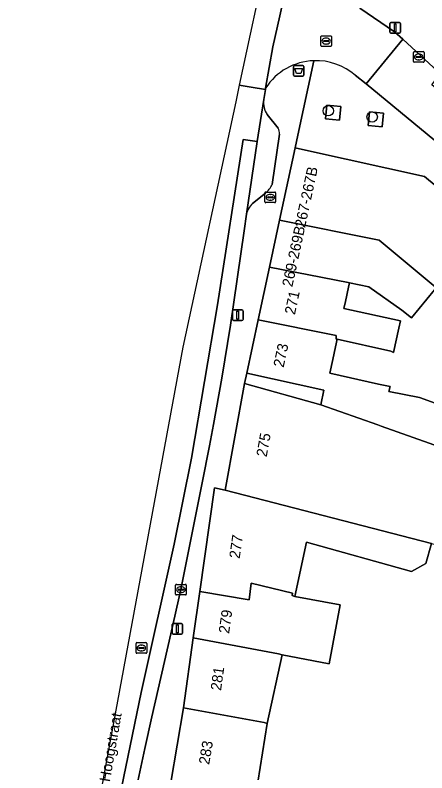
# Model space of a CAD drawing. Extents: x 160157 to 160921, y 381516 to 382045.
# Drawn here: x 160276.1 to 160314.8, y 381893.9 to 381965.1 of the extents above; entities that cross this region are included whole.
import ezdxf

# ---------------------------------------------------------------- set-up
doc = ezdxf.new("R2010")
doc.units = 0
for name, color, linetype in [('IMGEO_Afvalbak', 7, 'Continuous'), ('IMGEO_Boom', 7, 'Continuous'), ('IMGEO_Erf', 7, 'Continuous'), ('IMGEO_Kolk', 7, 'Continuous'), ('IMGEO_Lichtmast', 7, 'Continuous'), ('IMGEO_Openbare_ruimte_label', 7, 'Continuous'), ('IMGEO_Pand', 7, 'Continuous'), ('IMGEO_Pand_nummerreeks', 7, 'Continuous'), ('IMGEO_Parkeervlak_open', 7, 'Continuous'), ('IMGEO_Rijbaan_lokaal_gesloten', 7, 'Continuous'), ('IMGEO_Rijbaan_lokaal_open', 7, 'Continuous'), ('IMGEO_Rioolput', 7, 'Continuous'), ('IMGEO_Verkeerseiland_groen', 7, 'Continuous'), ('IMGEO_Voetpad_open', 7, 'Continuous')]:
    doc.layers.add(name, color=color, linetype=linetype)

msp = doc.modelspace()

# ---------------------------------------------------------------- linework, layer by layer
at = {"layer": 'IMGEO_Afvalbak'}
for p, q in [((160302.243, 381959.444), (160302.243, 381960.244)), ((160302.243, 381960.244), (160302.243, 381959.444)), ((160302.343, 381960.344), (160303.133, 381960.344)), ((160303.133, 381960.344), (160302.343, 381960.344)), ((160303.233, 381960.244), (160303.233, 381959.444)), ((160303.233, 381959.444), (160303.233, 381960.244)), ((160303.133, 381959.344), (160302.343, 381959.344)), ((160302.343, 381959.344), (160303.133, 381959.344))]:
    msp.add_line(p, q, dxfattribs=at)
msp.add_lwpolyline([(160302.386, 381960.058), (160303.09, 381960.058), (160302.941, 381959.588), (160302.535, 381959.588), (160302.386, 381960.058)], dxfattribs=at)
for centre, start, end in [((160302.343, 381960.244), 90, 180), ((160302.343, 381960.244), 90, 180), ((160303.133, 381960.244), 0, 90), ((160303.133, 381960.244), 360, 90), ((160302.343, 381959.444), 180, 270), ((160302.343, 381959.444), 180, 270), ((160303.133, 381959.444), 270, 0), ((160303.133, 381959.444), 270, 0)]:
    msp.add_arc(centre, 0.1, start, end, dxfattribs=at)
at = {"layer": 'IMGEO_Boom'}
for centre in [(160305.523, 381956.101), (160309.643, 381955.512)]:
    msp.add_circle(centre, 0.489, dxfattribs=at)
at = {"layer": 'IMGEO_Erf'}
for points in [[(160315.504, 381939.276), (160313.335, 381936.645), (160312.439, 381937.379), (160309.331, 381939.549), (160307.525, 381939.949), (160307.431, 381939.523), (160307.137, 381938.195), (160306.991, 381937.531), (160312.301, 381936.356), (160312.154, 381935.692), (160311.645, 381933.391), (160311.405, 381933.518), (160306.362, 381934.633), (160306.209, 381933.943), (160306.074, 381933.334), (160305.939, 381932.725), (160305.656, 381931.448), (160310.237, 381930.434), (160311.319, 381930.195), (160311.218, 381929.737), (160314.104, 381929.169), (160323.234, 381925.853)], [(160315.222, 381915.474), (160314.69, 381913.569), (160313.339, 381912.824), (160303.485, 381915.581), (160302.383, 381910.492), (160306.634, 381909.694), (160305.597, 381904.174), (160301.195, 381905.001), (160299.796, 381898.547), (160298.67, 381891.657)]]:
    msp.add_lwpolyline(points, dxfattribs=at)
msp.add_lwpolyline([(160297.869, 381931.467), (160297.644, 381930.479), (160304.815, 381928.497), (160305.117, 381929.863)], close=True, dxfattribs=at)
at = {"layer": 'IMGEO_Kolk'}
for p, q in [((160313.521, 381960.724), (160313.521, 381961.576)), ((160313.596, 381961.65), (160314.448, 381961.65)), ((160314.009, 381961.43), (160314.034, 381961.43)), ((160314.522, 381961.576), (160314.522, 381960.724)), ((160314.448, 381960.65), (160313.596, 381960.65)), ((160313.78, 381961.144), (160313.78, 381961.156)), ((160314.218, 381961.107), (160313.82, 381961.107)), ((160313.823, 381961.193), (160314.221, 381961.193)), ((160314.032, 381960.87), (160314.007, 381960.87)), ((160314.264, 381961.156), (160314.264, 381961.144)), ((160299.647, 381948.466), (160300.499, 381948.466)), ((160299.572, 381947.54), (160299.572, 381948.392)), ((160299.831, 381947.96), (160299.831, 381947.972)), ((160300.269, 381947.923), (160299.871, 381947.923)), ((160299.874, 381948.009), (160300.272, 381948.009)), ((160300.06, 381948.246), (160300.085, 381948.246)), ((160300.315, 381947.972), (160300.315, 381947.96)), ((160300.573, 381948.392), (160300.573, 381947.54)), ((160300.499, 381947.466), (160299.647, 381947.466)), ((160300.083, 381947.686), (160300.058, 381947.686)), ((160291.178, 381910.7), (160291.178, 381911.552)), ((160291.253, 381911.626), (160292.105, 381911.626)), ((160292.179, 381911.552), (160292.179, 381910.7)), ((160291.437, 381911.12), (160291.437, 381911.132)), ((160291.875, 381911.083), (160291.477, 381911.083)), ((160291.48, 381911.169), (160291.878, 381911.169)), ((160291.689, 381910.846), (160291.664, 381910.846)), ((160291.666, 381911.406), (160291.691, 381911.406)), ((160291.921, 381911.132), (160291.921, 381911.12)), ((160292.105, 381910.626), (160291.253, 381910.626))]:
    msp.add_line(p, q, dxfattribs=at)
for points in [[(160313.521, 381960.724), (160313.521, 381961.576)], [(160313.596, 381961.65), (160314.448, 381961.65)], [(160314.522, 381961.576), (160314.522, 381960.724)], [(160314.448, 381960.65), (160313.596, 381960.65)], [(160299.647, 381948.466), (160300.499, 381948.466)], [(160299.572, 381947.54), (160299.572, 381948.392)], [(160300.573, 381948.392), (160300.573, 381947.54)], [(160300.499, 381947.466), (160299.647, 381947.466)], [(160291.178, 381910.7), (160291.178, 381911.552)], [(160291.253, 381911.626), (160292.105, 381911.626)], [(160292.179, 381911.552), (160292.179, 381910.7)], [(160292.105, 381910.626), (160291.253, 381910.626)]]:
    msp.add_lwpolyline(points, dxfattribs=at)
for centre, radius, start, end in [((160313.598, 381961.574), 0.0765, 91.55205, 178.44795), ((160313.598, 381961.574), 0.0765, 91.55205, 178.44795), ((160314.446, 381961.574), 0.0765, 1.55205, 88.44795), ((160314.446, 381961.574), 0.0765, 1.55205, 88.44795), ((160313.598, 381960.726), 0.0765, 181.55205, 268.44795), ((160313.598, 381960.726), 0.0765, 181.55205, 268.44795), ((160313.82, 381961.153), 0.0403, 85.87752, 175.75265), ((160313.817, 381961.143), 0.0366, 178.93798, 274.71019), ((160314.221, 381961.15), 0.043, 264.86636, 352.45326), ((160314.225, 381961.155), 0.0386, 1.73085, 96.63898), ((160314.446, 381960.726), 0.0765, 271.55205, 358.44795), ((160314.446, 381960.726), 0.0765, 271.55205, 358.44795), ((160299.649, 381948.39), 0.0765, 91.55205, 178.44795), ((160299.649, 381948.39), 0.0765, 91.55205, 178.44795), ((160300.497, 381948.39), 0.0765, 1.55205, 88.44795), ((160300.497, 381948.39), 0.0765, 1.55205, 88.44795), ((160299.871, 381947.969), 0.0403, 85.87752, 175.75265), ((160299.868, 381947.959), 0.0366, 178.93798, 274.71019), ((160300.272, 381947.966), 0.043, 264.86636, 352.45326), ((160300.276, 381947.971), 0.0386, 1.73085, 96.63898), ((160299.649, 381947.542), 0.0765, 181.55205, 268.44795), ((160299.649, 381947.542), 0.0765, 181.55205, 268.44795), ((160300.497, 381947.542), 0.0765, 271.55205, 358.44795), ((160300.497, 381947.542), 0.0765, 271.55205, 358.44795), ((160291.255, 381911.55), 0.0765, 91.55205, 178.44795), ((160291.255, 381911.55), 0.0765, 91.55205, 178.44795), ((160292.103, 381911.55), 0.0765, 1.55205, 88.44795), ((160292.103, 381911.55), 0.0765, 1.55205, 88.44795), ((160291.477, 381911.129), 0.0403, 85.87752, 175.75265), ((160291.474, 381911.119), 0.0366, 178.93798, 274.71019), ((160291.878, 381911.126), 0.043, 264.86636, 352.45326), ((160291.882, 381911.131), 0.0386, 1.73085, 96.63898), ((160291.255, 381910.702), 0.0765, 181.55205, 268.44795), ((160291.255, 381910.702), 0.0765, 181.55205, 268.44795), ((160292.103, 381910.702), 0.0765, 271.55205, 358.44795), ((160292.103, 381910.702), 0.0765, 271.55205, 358.44795)]:
    msp.add_arc(centre, radius, start, end, dxfattribs=at)
for centre, major_axis, ratio, start_param, end_param in [((160314.008, 381961.15), (-0.387, 0.002), 0.722429, 4.712389, 7.853982), ((160314.033, 381961.15), (-0.39, 0.002), 0.717154, 1.570796, 4.712389), ((160300.059, 381947.966), (-0.387, 0.002), 0.722429, 4.712389, 7.853982), ((160300.084, 381947.966), (-0.39, 0.002), 0.717154, 1.570796, 4.712389), ((160291.665, 381911.126), (-0.387, 0.002), 0.722429, 4.712389, 7.853982), ((160291.69, 381911.126), (-0.39, 0.002), 0.717154, 1.570796, 4.712389)]:
    msp.add_ellipse(centre, major_axis=major_axis, ratio=ratio, start_param=start_param, end_param=end_param, dxfattribs=at)
at = {"layer": 'IMGEO_Lichtmast'}
for p, q in [((160311.309, 381963.491), (160311.309, 381964.291)), ((160311.309, 381964.291), (160311.309, 381963.491)), ((160311.409, 381964.391), (160312.199, 381964.391)), ((160312.199, 381964.391), (160311.409, 381964.391)), ((160312.299, 381964.291), (160312.299, 381963.491)), ((160312.299, 381963.491), (160312.299, 381964.291)), ((160312.199, 381963.391), (160311.409, 381963.391)), ((160311.409, 381963.391), (160312.199, 381963.391)), ((160296.526, 381936.491), (160296.526, 381937.291)), ((160296.526, 381937.291), (160296.526, 381936.491)), ((160296.626, 381937.391), (160297.416, 381937.391)), ((160297.416, 381937.391), (160296.626, 381937.391)), ((160297.516, 381937.291), (160297.516, 381936.491)), ((160297.516, 381936.491), (160297.516, 381937.291)), ((160297.416, 381936.391), (160296.626, 381936.391)), ((160296.626, 381936.391), (160297.416, 381936.391)), ((160290.95, 381907.951), (160291.74, 381907.951)), ((160291.74, 381907.951), (160290.95, 381907.951)), ((160290.85, 381907.051), (160290.85, 381907.851)), ((160290.85, 381907.851), (160290.85, 381907.051)), ((160291.84, 381907.851), (160291.84, 381907.051)), ((160291.84, 381907.051), (160291.84, 381907.851)), ((160291.74, 381906.951), (160290.95, 381906.951)), ((160290.95, 381906.951), (160291.74, 381906.951))]:
    msp.add_line(p, q, dxfattribs=at)
for points in [[(160311.729, 381964.266), (160311.879, 381964.266), (160311.879, 381963.516), (160311.729, 381963.516), (160311.729, 381964.266)], [(160296.946, 381937.266), (160297.096, 381937.266), (160297.096, 381936.516), (160296.946, 381936.516), (160296.946, 381937.266)], [(160291.27, 381907.826), (160291.42, 381907.826), (160291.42, 381907.076), (160291.27, 381907.076), (160291.27, 381907.826)]]:
    msp.add_lwpolyline(points, dxfattribs=at)
for centre, start, end in [((160311.409, 381964.291), 90, 180), ((160311.409, 381964.291), 90, 180), ((160312.199, 381964.291), 0, 90), ((160312.199, 381964.291), 360, 90), ((160311.409, 381963.491), 180, 270), ((160311.409, 381963.491), 180, 270), ((160312.199, 381963.491), 270, 0), ((160312.199, 381963.491), 270, 0), ((160296.626, 381937.291), 90, 180), ((160296.626, 381937.291), 90, 180), ((160297.416, 381937.291), 0, 90), ((160297.416, 381937.291), 360, 90), ((160296.626, 381936.491), 180, 270), ((160296.626, 381936.491), 180, 270), ((160297.416, 381936.491), 270, 0), ((160297.416, 381936.491), 270, 0), ((160290.95, 381907.851), 90, 180), ((160290.95, 381907.851), 90, 180), ((160291.74, 381907.851), 0, 90), ((160291.74, 381907.851), 360, 90), ((160290.95, 381907.051), 180, 270), ((160290.95, 381907.051), 180, 270), ((160291.74, 381907.051), 270, 0), ((160291.74, 381907.051), 270, 0)]:
    msp.add_arc(centre, 0.1, start, end, dxfattribs=at)
at = {"layer": 'IMGEO_Pand'}
for points in [[(160314.547, 381949.911), (160303.648, 381952.346), (160302.402, 381952.62), (160300.943, 381945.827), (160310.305, 381943.95), (160315.932, 381939.263), (160317.394, 381941.086), (160320.396, 381944.729), (160320.573, 381944.944)], [(160310.305, 381943.95), (160300.943, 381945.827), (160299.997, 381941.422), (160307.388, 381939.979), (160307.525, 381939.949), (160309.331, 381939.549), (160312.439, 381937.379), (160313.335, 381936.645), (160315.504, 381939.276), (160315.768, 381939.058), (160315.932, 381939.263)], [(160307.431, 381939.523), (160307.525, 381939.949), (160307.388, 381939.979), (160299.997, 381941.422), (160298.94, 381936.479), (160306.273, 381935.002), (160306.247, 381934.658), (160306.362, 381934.633), (160311.405, 381933.518), (160311.645, 381933.391), (160312.154, 381935.692), (160312.301, 381936.356), (160306.991, 381937.531), (160307.137, 381938.195)], [(160306.362, 381934.633), (160306.247, 381934.658), (160306.273, 381935.002), (160298.94, 381936.479), (160297.869, 381931.467), (160305.117, 381929.863), (160304.815, 381928.497), (160310.186, 381926.596), (160310.498, 381926.485), (160320.481, 381922.951), (160321.987, 381922.418), (160323.234, 381925.853), (160314.104, 381929.169), (160311.218, 381929.737), (160311.319, 381930.195), (160310.237, 381930.434), (160305.656, 381931.448), (160305.939, 381932.725), (160306.074, 381933.334), (160306.209, 381933.943)], [(160310.498, 381926.485), (160310.186, 381926.596), (160304.815, 381928.497), (160297.644, 381930.479), (160295.847, 381920.47), (160315.222, 381915.474), (160319.03, 381914.492), (160319.065, 381914.694), (160320.415, 381922.565), (160320.481, 381922.951)], [(160303.485, 381915.581), (160313.339, 381912.824), (160314.69, 381913.569), (160315.222, 381915.474), (160295.847, 381920.47), (160294.829, 381920.702), (160293.452, 381910.947), (160298.077, 381910.156), (160298.29, 381911.74), (160302.165, 381910.806), (160302.119, 381910.583), (160302.383, 381910.492)], [(160302.383, 381910.492), (160302.119, 381910.583), (160302.165, 381910.806), (160298.29, 381911.74), (160298.077, 381910.156), (160293.452, 381910.947), (160292.84, 381906.609), (160300.844, 381905.105), (160301.195, 381905.001), (160305.597, 381904.174), (160306.634, 381909.694)], [(160291.909, 381900.018), (160299.499, 381898.659), (160299.796, 381898.547), (160301.195, 381905.001), (160300.844, 381905.105), (160292.84, 381906.609)], [(160291.909, 381900.018), (160290.73, 381893.015), (160298.67, 381891.657), (160299.796, 381898.547), (160299.499, 381898.659)]]:
    msp.add_lwpolyline(points, close=True, dxfattribs=at)
at = {"layer": 'IMGEO_Parkeervlak_open'}
for points in [[(160299.468, 381957.153), (160298.833, 381953.198), (160297.847, 381946.391)], [(160300.804, 381954.461), (160299.777, 381955.735)], [(160300.245, 381949.175), (160300.936, 381953.898)], [(160298.408, 381947.384), (160299.612, 381948.351)]]:
    msp.add_lwpolyline(points, dxfattribs=at)
for centre, radius, start, end in [((160301.579, 381956.87), 2.13, 172.37795, 212.20862), ((160300.032, 381953.983), 0.908, 354.63299, 31.75727), ((160298.073, 381950.188), 2.396, 309.94626, 334.99052), ((160299.547, 381946.086), 1.727, 131.25281, 169.81823)]:
    msp.add_arc(centre, radius, start, end, dxfattribs=at)
at = {"layer": 'IMGEO_Rijbaan_lokaal_gesloten'}
for points in [[(160297.164, 381958.502), (160297.164, 381958.502), (160298.281, 381958.318), (160299.617, 381958.101), (160299.638, 381958.223), (160300.303, 381962.088), (160303.083, 381974.326), (160304.41, 381976.336), (160306.384, 381980.075), (160307.059, 381981.3), (160305.62, 381982.089), (160304.281, 381982.823), (160304.281, 381982.823), (160301.32, 381977.785), (160299.825, 381970.848), (160297.164, 381958.502)], [(160287.643, 381893.136), (160288.303, 381896.223), (160288.953, 381899.178), (160290.743, 381906.966), (160291.673, 381911.126), (160293.687, 381921.156), (160294.358, 381924.643), (160294.732, 381926.626), (160295.519, 381930.982), (160296.339, 381935.958), (160297.622, 381944.834), (160297.847, 381946.391), (160298.833, 381953.198), (160297.516, 381953.389), (160295.111, 381937.88), (160292.664, 381923.46), (160291.032, 381915.39), (160287.95, 381901.47), (160283.011, 381877.485)]]:
    msp.add_lwpolyline(points, dxfattribs=at)
msp.add_lwpolyline([(160276.109, 381847.711), (160277.474, 381847.414), (160279.431, 381857.399), (160281.062, 381866.83), (160283.011, 381877.485), (160287.95, 381901.47), (160291.032, 381915.39), (160292.664, 381923.46), (160295.111, 381937.88), (160297.516, 381953.389), (160298.833, 381953.198), (160299.468, 381957.153), (160299.617, 381958.101), (160298.281, 381958.318), (160297.164, 381958.502), (160297.164, 381958.502), (160296.824, 381956.927), (160291.857, 381933.882), (160277.856, 381858.1)], close=True, dxfattribs=at)
at = {"layer": 'IMGEO_Rijbaan_lokaal_open'}
for points in [[(160303.659, 381973.194), (160304.41, 381976.336), (160303.083, 381974.326), (160300.303, 381962.088), (160299.638, 381958.223)], [(160308.058, 381959.424), (160309.064, 381958.612), (160312.536, 381962.804), (160311.735, 381963.499), (160308.469, 381965.745)], [(160360.149, 381921.379), (160351.289, 381928.805), (160315.245, 381958.534), (160315.541, 381958.892), (160316.098, 381959.567), (160315.4, 381960.173), (160312.536, 381962.804), (160309.064, 381958.612), (160359.924, 381916.684), (160369.605, 381914.849), (160369.748, 381915.384)]]:
    msp.add_lwpolyline(points, dxfattribs=at)
for centre, radius, start, end in [((160304.354, 381955.2), 5.602, 91.99263, 147.33595), ((160304.383, 381955.216), 5.587, 48.8731, 92.30218)]:
    msp.add_arc(centre, radius, start, end, dxfattribs=at)
at = {"layer": 'IMGEO_Rioolput'}
for p, q in [((160304.819, 381962.21), (160304.819, 381963.062)), ((160304.894, 381963.136), (160305.746, 381963.136)), ((160305.307, 381962.916), (160305.332, 381962.916)), ((160305.82, 381963.062), (160305.82, 381962.21)), ((160305.746, 381962.136), (160304.894, 381962.136)), ((160305.078, 381962.63), (160305.078, 381962.642)), ((160305.516, 381962.593), (160305.118, 381962.593)), ((160305.121, 381962.679), (160305.519, 381962.679)), ((160305.33, 381962.356), (160305.305, 381962.356)), ((160305.562, 381962.642), (160305.562, 381962.63)), ((160287.465, 381905.223), (160287.465, 381906.075)), ((160287.54, 381906.149), (160288.392, 381906.149)), ((160287.953, 381905.929), (160287.978, 381905.929)), ((160288.466, 381906.075), (160288.466, 381905.223)), ((160288.392, 381905.149), (160287.54, 381905.149)), ((160287.724, 381905.643), (160287.724, 381905.655)), ((160288.162, 381905.606), (160287.764, 381905.606)), ((160287.767, 381905.692), (160288.165, 381905.692)), ((160287.976, 381905.369), (160287.951, 381905.369)), ((160288.208, 381905.655), (160288.208, 381905.643))]:
    msp.add_line(p, q, dxfattribs=at)
for points in [[(160304.819, 381962.21), (160304.819, 381963.062)], [(160304.894, 381963.136), (160305.746, 381963.136)], [(160305.82, 381963.062), (160305.82, 381962.21)], [(160305.746, 381962.136), (160304.894, 381962.136)], [(160287.465, 381905.223), (160287.465, 381906.075)], [(160287.54, 381906.149), (160288.392, 381906.149)], [(160288.466, 381906.075), (160288.466, 381905.223)], [(160288.392, 381905.149), (160287.54, 381905.149)]]:
    msp.add_lwpolyline(points, dxfattribs=at)
for centre, radius, start, end in [((160304.896, 381963.06), 0.0765, 91.55205, 178.44795), ((160304.896, 381963.06), 0.0765, 91.55205, 178.44795), ((160305.744, 381963.06), 0.0765, 1.55205, 88.44795), ((160305.744, 381963.06), 0.0765, 1.55205, 88.44795), ((160304.896, 381962.212), 0.0765, 181.55205, 268.44795), ((160304.896, 381962.212), 0.0765, 181.55205, 268.44795), ((160305.118, 381962.639), 0.0403, 85.87752, 175.75265), ((160305.115, 381962.629), 0.0366, 178.93798, 274.71019), ((160305.519, 381962.636), 0.043, 264.86636, 352.45326), ((160305.523, 381962.641), 0.0386, 1.73085, 96.63898), ((160305.744, 381962.212), 0.0765, 271.55205, 358.44795), ((160305.744, 381962.212), 0.0765, 271.55205, 358.44795), ((160287.542, 381906.073), 0.0765, 91.55205, 178.44795), ((160287.542, 381906.073), 0.0765, 91.55205, 178.44795), ((160288.39, 381906.073), 0.0765, 1.55205, 88.44795), ((160288.39, 381906.073), 0.0765, 1.55205, 88.44795), ((160287.542, 381905.225), 0.0765, 181.55205, 268.44795), ((160287.542, 381905.225), 0.0765, 181.55205, 268.44795), ((160287.764, 381905.652), 0.0403, 85.87752, 175.75265), ((160287.761, 381905.642), 0.0366, 178.93798, 274.71019), ((160288.165, 381905.649), 0.043, 264.86636, 352.45326), ((160288.169, 381905.654), 0.0386, 1.73085, 96.63898), ((160288.39, 381905.225), 0.0765, 271.55205, 358.44795), ((160288.39, 381905.225), 0.0765, 271.55205, 358.44795)]:
    msp.add_arc(centre, radius, start, end, dxfattribs=at)
for centre, major_axis, ratio, start_param, end_param in [((160305.306, 381962.636), (-0.387, 0.002), 0.722429, 4.712389, 7.853982), ((160305.331, 381962.636), (-0.39, 0.002), 0.717154, 1.570796, 4.712389), ((160287.952, 381905.649), (-0.387, 0.002), 0.722429, 4.712389, 7.853982), ((160287.977, 381905.649), (-0.39, 0.002), 0.717154, 1.570796, 4.712389)]:
    msp.add_ellipse(centre, major_axis=major_axis, ratio=ratio, start_param=start_param, end_param=end_param, dxfattribs=at)
at = {"layer": 'IMGEO_Verkeerseiland_groen'}
for points in [[(160306.693, 381956.503), (160305.399, 381956.627), (160305.275, 381955.333), (160306.569, 381955.209)], [(160310.697, 381955.884), (160309.403, 381956.009), (160309.279, 381954.715), (160310.572, 381954.59)]]:
    msp.add_lwpolyline(points, close=True, dxfattribs=at)
at = {"layer": 'IMGEO_Voetpad_open'}
for points in [[(160308.469, 381965.745), (160311.735, 381963.499), (160312.536, 381962.804), (160315.4, 381960.173)], [(160292.84, 381906.609), (160293.452, 381910.947), (160294.829, 381920.702), (160295.847, 381920.47), (160297.644, 381930.479), (160297.869, 381931.467), (160298.94, 381936.479), (160299.997, 381941.422), (160300.943, 381945.827), (160302.402, 381952.62), (160302.654, 381953.794), (160304.159, 381960.798)], [(160304.159, 381960.798), (160302.654, 381953.794), (160302.402, 381952.62), (160303.648, 381952.346), (160314.547, 381949.911), (160320.573, 381944.944), (160320.396, 381944.729), (160321.073, 381944.178), (160326.419, 381939.772), (160331.466, 381935.613), (160336.75, 381931.258), (160337.94, 381930.325), (160340.102, 381928.629), (160344.499, 381924.996), (160348.857, 381921.395), (160349.638, 381920.772), (160353.572, 381917.522), (160357.461, 381914.308), (160358.404, 381913.522), (160362.436, 381910.191), (160366.268, 381907.024)], [(160369.605, 381914.849), (160359.924, 381916.684), (160309.064, 381958.612), (160308.058, 381959.424)], [(160299.638, 381958.223), (160299.617, 381958.101), (160299.468, 381957.153)], [(160299.777, 381955.735), (160300.804, 381954.461)], [(160300.936, 381953.898), (160300.245, 381949.175)], [(160299.612, 381948.351), (160298.408, 381947.384)], [(160297.847, 381946.391), (160297.622, 381944.834), (160296.339, 381935.958), (160295.519, 381930.982), (160294.732, 381926.626), (160294.358, 381924.643), (160293.687, 381921.156), (160291.673, 381911.126), (160290.743, 381906.966), (160288.953, 381899.178), (160288.303, 381896.223), (160287.643, 381893.136)], [(160278.871, 381847.11), (160283.566, 381846.417), (160283.791, 381847.596), (160285.021, 381854.491), (160286.017, 381860.074), (160287.615, 381869.031), (160288.207, 381872.123), (160287.237, 381872.281), (160288.451, 381879.486), (160289.614, 381886.39), (160290.73, 381893.015), (160291.909, 381900.018), (160292.84, 381906.609)]]:
    msp.add_lwpolyline(points, dxfattribs=at)
for points in [[(160305.275, 381955.333), (160305.399, 381956.627), (160306.693, 381956.503), (160306.569, 381955.209)], [(160309.279, 381954.715), (160309.403, 381956.009), (160310.697, 381955.884), (160310.572, 381954.59)]]:
    msp.add_lwpolyline(points, close=True, dxfattribs=at)
for centre, radius, start, end in [((160304.354, 381955.2), 5.602, 91.99263, 147.33595), ((160304.383, 381955.216), 5.587, 48.8731, 92.30218), ((160301.579, 381956.87), 2.13, 172.37795, 212.20862), ((160300.032, 381953.983), 0.908, 354.63299, 31.75727), ((160298.073, 381950.188), 2.396, 309.94626, 334.99052), ((160299.547, 381946.086), 1.727, 131.25281, 169.81823)]:
    msp.add_arc(centre, radius, start, end, dxfattribs=at)

# ---------------------------------------------------------------- texts
at = {"layer": 'IMGEO_Openbare_ruimte_label'}
msp.add_text('Hoogstraat', height=1, rotation=80.15138, dxfattribs=at).set_placement((160285.001, 381893.028))
at = {"layer": 'IMGEO_Pand_nummerreeks'}
for s, rotation, p in [('267-267B', 77.87642, (160303.335, 381945.057)), ('269-269B', 77.88215, (160302.14, 381939.494)), ('271', 77.90507, (160302.383, 381936.892)), ('273', 77.93945, (160301.323, 381931.94)), ('275', 79.82448, (160299.731, 381923.538)), ('277', 81.96734, (160297.196, 381914.001)), ('279', 81.96734, (160296.202, 381906.955)), ('281', 81.95998, (160295.445, 381901.602)), ('283', 80.43889, (160294.33, 381894.647))]:
    msp.add_text(s, height=1, rotation=rotation, dxfattribs=at).set_placement(p)

doc.saveas('drawing.dxf')
